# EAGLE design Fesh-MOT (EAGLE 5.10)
MFG: Nippon Chemi; PN: APXE160ARA390ME61G

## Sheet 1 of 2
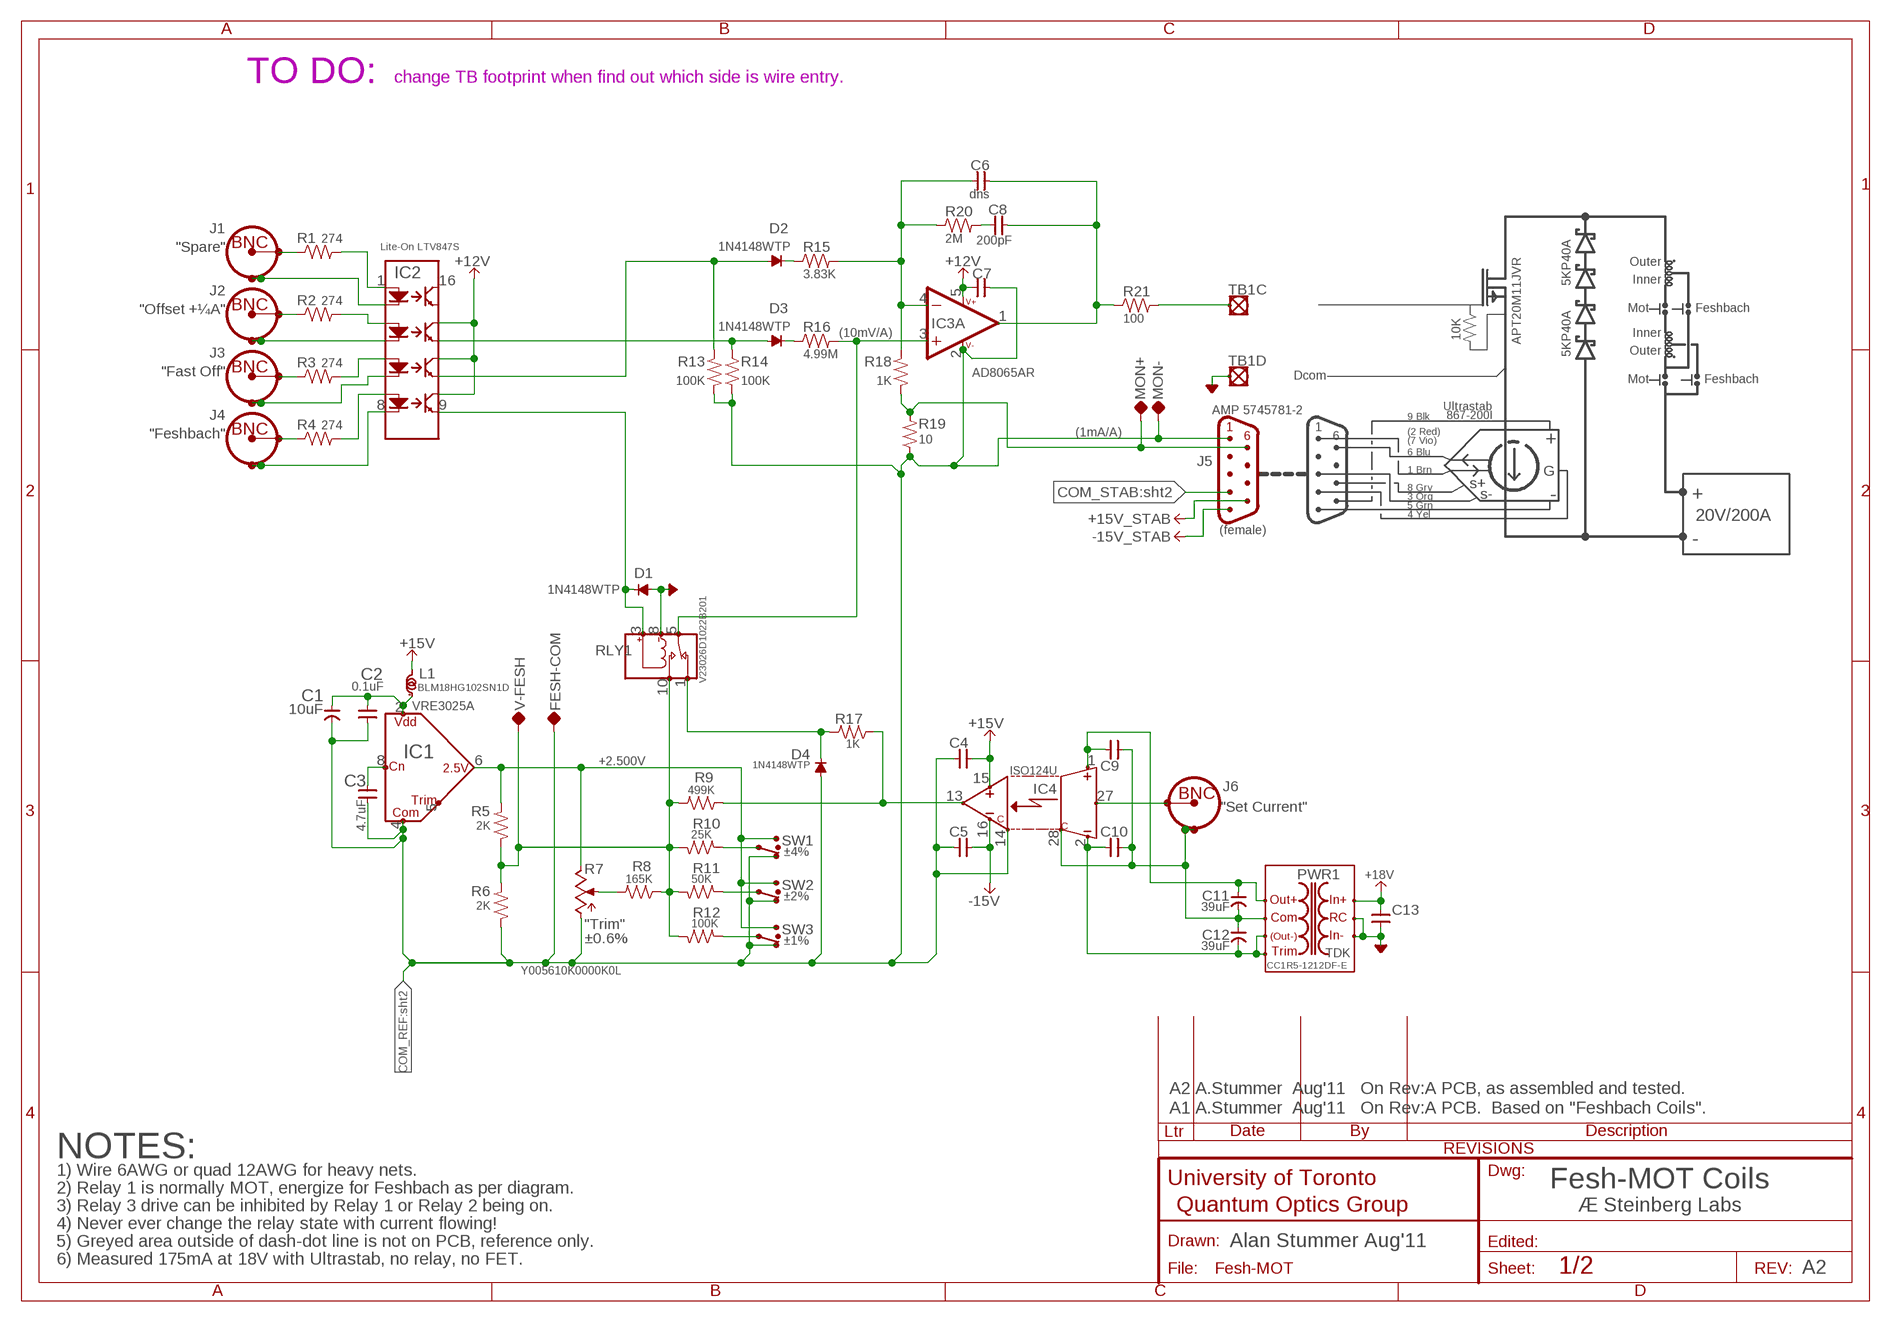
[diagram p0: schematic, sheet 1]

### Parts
C1  10uF  CAP-POL--NICHICON_F91_C  [CAP:NICHICON_F91_C]
C2  0.1uF  CAP-V-0805  [2012(0805)]
C3  4.7uF  CAP-V-0805  [2012(0805)]
C4  0.1uF  CAP-H-0805  [2012(0805)]
C5  0.1uF  CAP-H-0805  [2012(0805)]
C6  dns  CAP-H-0805  [2012(0805)]
C7  0.1uF  CAP-H-0805  [2012(0805)]
C8  200pF  CAP-H-0805  [2012(0805)]
C9  0.1uF  CAP-H-0805  [2012(0805)]
C10  0.1uF  CAP-H-0805  [2012(0805)]
C11  39uF  CAP-POL--NIPPONCHEM_E61  [CAP:NIPPONCHEM_E61]
C12  39uF  CAP-POL--NIPPONCHEM_E61  [CAP:NIPPONCHEM_E61]
C13  0.1uF  CAP-H-0805  [2012(0805)]
D1  1N4148WTP  DIODE,GENERIC-SOD123  [SOD123]
D2  1N4148WTP  DIODE,GENERIC-SOD123  [SOD123]
D3  1N4148WTP  DIODE,GENERIC-SOD123  [SOD123]
D4  1N4148WTP  DIODE,GENERIC-SOD123  [SOD123]
FESH-COM  TP-0.052"  [TP-0.052]
IC1  VRE3025A  VRE3025(2.5V_PRECISION_REF)  [THALER_SMT8]
IC2  Lite-On LTV847S  PC847P  [DIL16]
IC3  AD8065AR  OPAMP-SOT23-5  [SOT23-5]
IC4  ISO124U  ANALOG:ISOLATOR_ISO12X-SOIC28B  [SOIC28B]
J1  CONN-BNCTYPE3HORIZ  [CONN-BNC-AMP-TYPE3HORIZ]
J2  CONN-BNCTYPE3HORIZ  [CONN-BNC-AMP-TYPE3HORIZ]
J3  CONN-BNCTYPE3HORIZ  [CONN-BNC-AMP-TYPE3HORIZ]
J4  CONN-BNCTYPE3HORIZ  [CONN-BNC-AMP-TYPE3HORIZ]
J5  AMP 5745781-2  CONN:DB9-#2-AMP_745131  [CONN:DB9-H/V1]
J6  CONN-BNCTYPE3HORIZ  [CONN-BNC-AMP-TYPE3HORIZ]
L1  BLM18HG102SN1D  INDUCTOR-0603  [1608(0603)]
MON+  TP-0.052"  [TP-0.052]
MON-  TP-0.052"  [TP-0.052]
PWR1  CC1R5-1212DF-E  DC-DC:CCP-__-E(TDK1.5-25W)-CC1R5-R-E  [DC-DC:CC1R5-XXXXX-R-E(TDK/LAMBDA)]
R1  274  R-H-0805  [2012(0805)]
R2  274  R-H-0805  [2012(0805)]
R3  274  R-H-0805  [2012(0805)]
R4  274  R-H-0805  [2012(0805)]
R5  2K  R-V-Z201(TEXASCOMPONENTS)  [RES:Z201_TEXASCOMPONENTS]
R6  2K  R-V-Z201(TEXASCOMPONENTS)  [RES:Z201_TEXASCOMPONENTS]
R7  Y005610K0000K0L  POT-BOURNS_3009P  [BOURNS_3009P]
R8  165K  R-V-5025(2010)(DOWN-TO-0805)  [5025(2010)(DOWN-TO-0805)]
R9  499K  R-V-0805  [2012(0805)]
R10  25K  R-V-VH_02(TEXASCOMPONENTS)  [RES:VH_02,TEXASCOMPONENTS]
R11  50K  R-V-VH_02(TEXASCOMPONENTS)  [RES:VH_02,TEXASCOMPONENTS]
R12  100K  R-V-VH_02(TEXASCOMPONENTS)  [RES:VH_02,TEXASCOMPONENTS]
R13  100K  R-V-0805  [2012(0805)]
R14  100K  R-V-0805  [2012(0805)]
R15  3.83K  R-H-0805  [2012(0805)]
R16  4.99M  R-H-0805  [2012(0805)]
R17  1K  R-V-0805  [2012(0805)]
R18  1K  R-V-0805  [2012(0805)]
R19  10  R-V-Z206(TEXASCOMPONENTS)  [RES:Z206_TEXASCOMPONENTS]
R20  2M  R-H-0805  [2012(0805)]
R21  100  R-H-0805  [2012(0805)]
RLY1  V23026D1022B201  RELAY:SPDT-TYCO_V23026(SMT)  [RELAY:SPDT-TYCO_V23026]
SW1  ±4%  SWITCH:SPDT_CJS-1200A1  [SWITCH:SPDT-DIP(COPAL)]
SW2  ±2%  SWITCH:SPDT_CJS-1200A1  [SWITCH:SPDT-DIP(COPAL)]
SW3  ±1%  SWITCH:SPDT_CJS-1200A1  [SWITCH:SPDT-DIP(COPAL)]
TB1  TB-4-TYCO_1776244-4  [TB,BARRIER:1776244-4(TYCO,4,PCB,5MM)]
V-FESH  TP-0.052"  [TP-0.052]

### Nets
+2.500V: IC1.6(OUT) R5.THIS R7.CW SW1.1(NO\UP\RIGHT) SW2.1(NO\UP\RIGHT) SW3.1(NO\UP\RIGHT)
+12V [Wider]: C7.1 IC2.10(C4) IC2.12(C3) IC2.14(C2) IC3.5(B:V++) ; also sheet 2
+15V [Wider]: C4.1 IC4.15(OUT+V) L1.2(B) ; also sheet 2
+15V_STAB [Wider]: J5.9 ; also sheet 2
+15VA: C9.2 C11.POS IC4.1(IN+V) PWR1.+VOUT(+OUT)
+18V [Wider]: C13.1 PWR1.+VIN(+IN) ; also sheet 2
-15V: C5.1 IC4.16(OUT-V)
-15V_STAB [Wider]: J5.5 ; also sheet 2
-15VA: C10.2 C12.NEG IC4.2(IN-V) PWR1.-VOUT(-OUT) PWR1.TRM(TRIM)
AGND: C13.2 D1.A PWR1.-VIN(-IN) PWR1.RC RLY1.8(COIL-) TB1.4 ; also sheet 2
COM-A: C9.1 C10.1 C11.NEG C12.POS IC4.28(IN-COM) J6.SHIELD1 J6.SHIELD2 PWR1.COM
COM_REF [Wider]: C1.-(NEG) C2.1 C3.1 C4.2 C5.2 C7.2 D4.A FESH-COM.TP IC1.4(COM) IC3.2(B:V-) IC4.14(OUT-COM) J5.1 MON-.TP R6.OTHER R7.CCW R13.1 R14.1 R19.OTHER SW1.2(NC\DOWN\LEFT) SW2.2(NC\DOWN\LEFT) SW3.2(NC\DOWN\LEFT) ; also sheet 2
COM_STAB [Wider]: J5.4 ; also sheet 2
DRV: C6.2 C8.2 IC3.1(A:OUT) R21.1
N$1: C3.2 IC1.8(NOISECAP)
N$2 [Wider]: J5.6 MON+.TP R18.1 R19.THIS
N$4: J1.CONDUCTOR R1.1
N$5: D4.C R17.2 RLY1.1(NC)
N$6: J2.CONDUCTOR R2.1
N$7: IC4.13(OUT) R9.1 R17.1
N$8: C6.1 IC3.4(A:-IN) R15.2 R18.2 R20.1
N$10: J3.CONDUCTOR R3.1
N$11: R5.OTHER R6.THIS R8.1 R9.2 R10.2 R11.2 R12.2 RLY1.10(NO) V-FESH.TP
N$12: J4.CONDUCTOR R4.1
N$13: IC2.1(A1) R1.2
N$15: D3.A IC2.13(E2) R14.2
N$16: D1.C IC2.9(E4) RLY1.3(COIL+)
N$17: IC3.3(A:+IN) R16.2 RLY1.5(COM)
N$18: IC2.3(A2) R2.2
N$19: C1.+(POS) C2.2 IC1.2(VDD) L1.1(A)
N$20: D3.C R16.1
N$21: IC2.5(A3) R3.2
N$22: IC2.7(A4) R4.2
N$23: IC4.27(IN) J6.CONDUCTOR
N$24: C8.1 R20.2
N$25: R10.1 SW1.COM
N$26: R7.WIPER(W) R8.2
N$28: IC2.2(K1) J1.SHIELD1 J1.SHIELD2
N$29: IC2.4(K2) J2.SHIELD1 J2.SHIELD2
N$31: IC2.6(K3) J3.SHIELD1 J3.SHIELD2
N$32: R11.1 SW2.COM
N$33: R12.1 SW3.COM
N$42: R21.2 TB1.3
N$43: IC2.8(K4) J4.SHIELD1 J4.SHIELD2
N$45: D2.C R15.1
OFF: D2.A IC2.11(E3) R13.2
Unconnected: IC1.5(TRIM) IC2.15(E1) IC2.16(C1) J5.2 J5.3 J5.7 J5.8

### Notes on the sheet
- TO DO: | change TB footprint when find out which side is wire entry.
- "Spare"
- Outer
- 5KP40A | Inner
- "Offset +¼A" | Mot | Feshbach
- 10K
- (10mV/A) | Inner
- APT20M11JVR
- 5KP40A | Outer
- "Fast Off"
- Dcom
- Mot | Feshbach
- Ultrastab
- 9 Blk | 867-200I
- 1
- (1mA/A) | (2 Red)
- "Feshbach" | 6
- (7 Vio) | +
- 6 Blu
- 1 Brn | G
- 8 Gry | s+
- 3 Org | s- | - | +
- 5 Grn
- 4 Yel
- 20V/200A
- (female)
- -
- "Set Current"
- "Trim"
- ±0.6%
- A2 A.Stummer  Aug'11   On Rev:A PCB, as assembled and tested.
- A1 A.Stummer  Aug'11   On Rev:A PCB.  Based on "Feshbach Coils".
- NOTES:
- 1) Wire 6AWG or quad 12AWG for heavy nets.
- Fesh-MOT Coils
- 2) Relay 1 is normally MOT, energize for Feshbach as per diagram.
- 3) Relay 3 drive can be inhibited by Relay 1 or Relay 2 being on. | Æ Steinberg Labs
- 4) Never ever change the relay state with current flowing!
- 5) Greyed area outside of dash-dot line is not on PCB, reference only. | Alan Stummer Aug'11
- 6) Measured 175mA at 18V with Ultrastab, no relay, no FET.
- A2

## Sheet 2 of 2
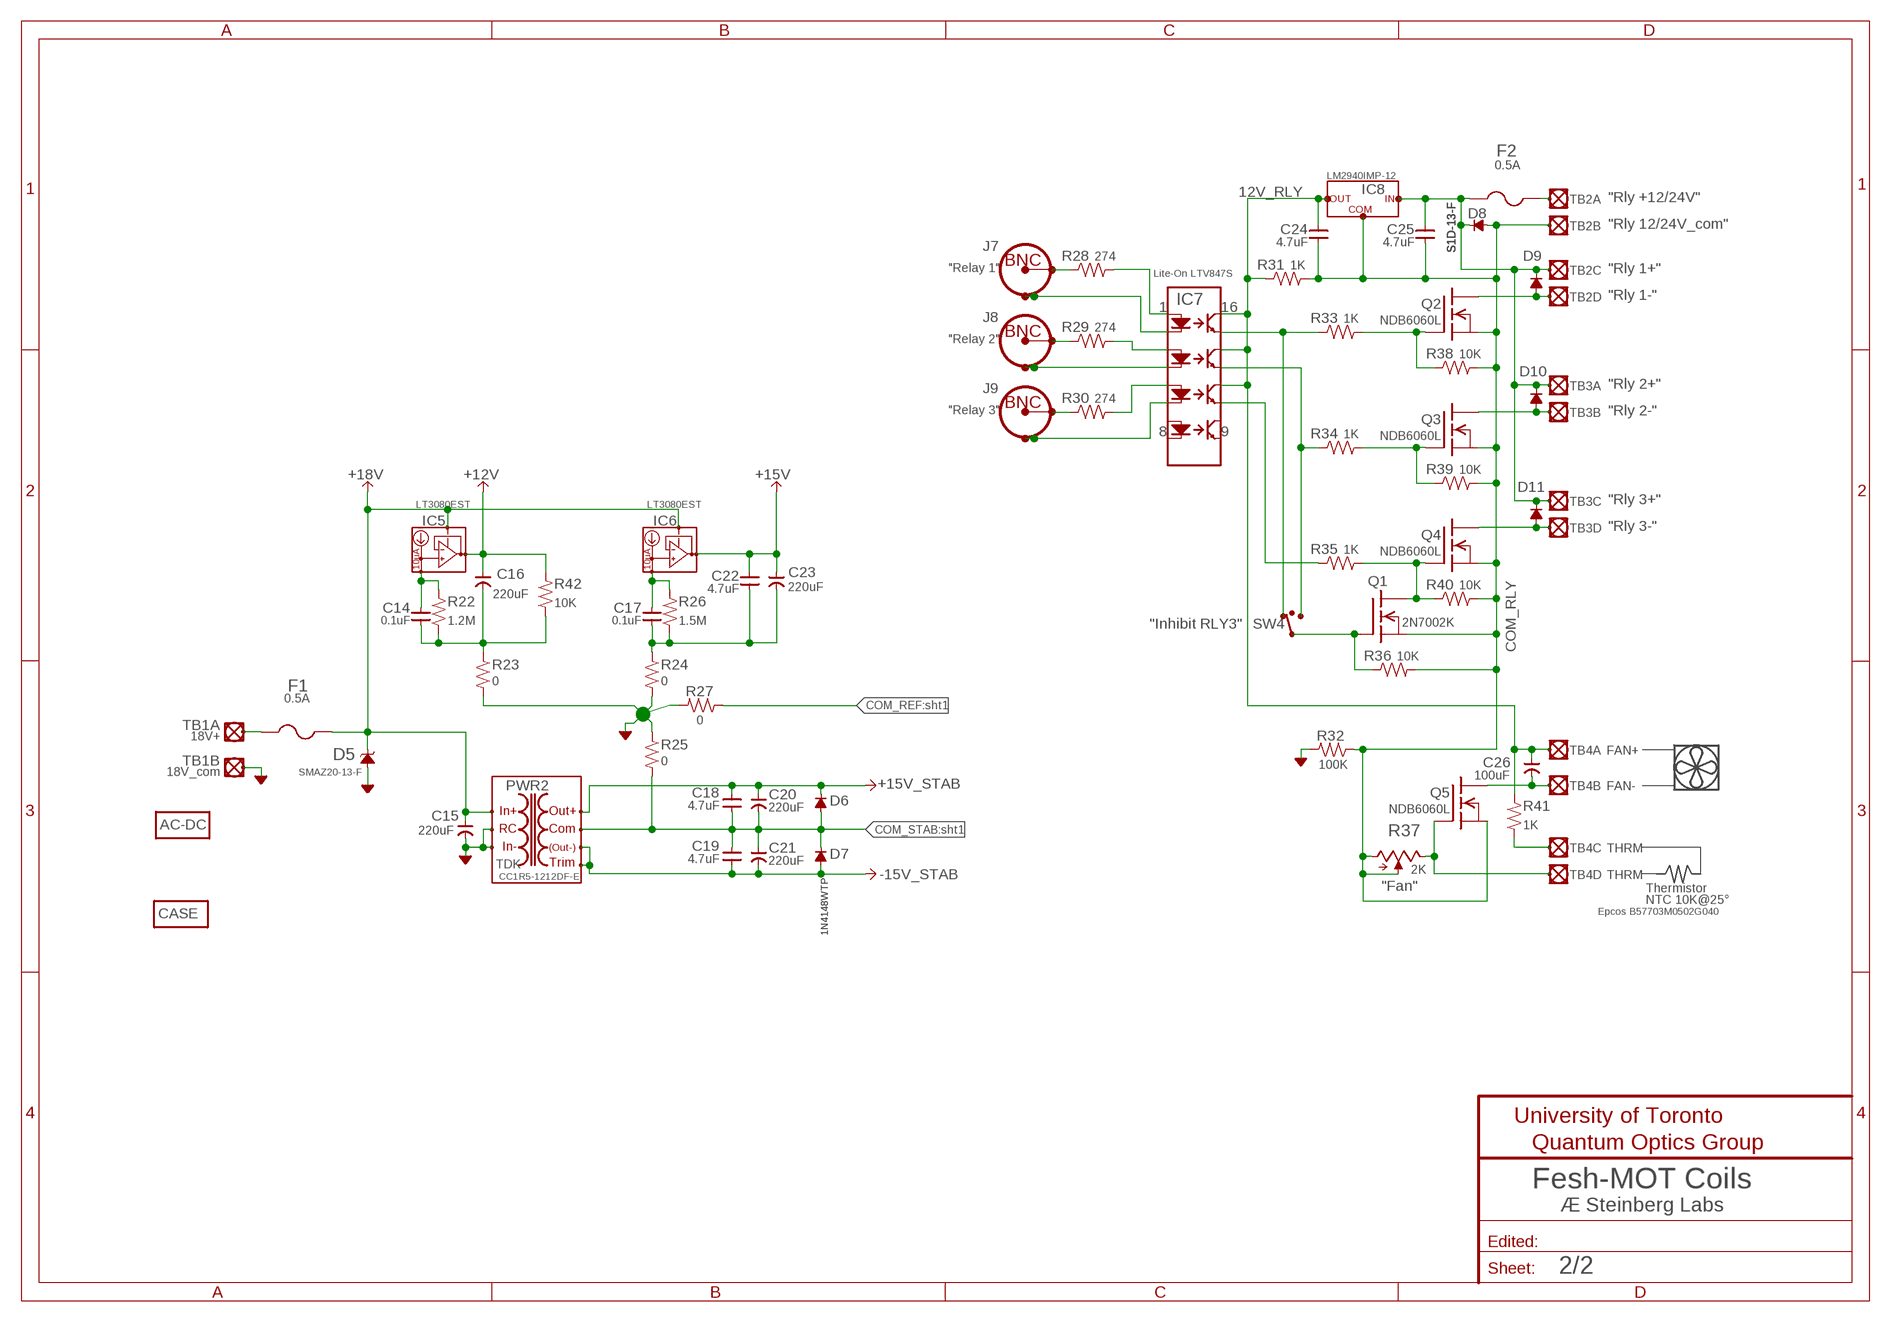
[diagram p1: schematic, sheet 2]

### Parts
AC-DC  MISC  [MISC]
C14  0.1uF  CAP-V-0805  [2012(0805)]
C15  220uF  CAP-POL--NIPPONCHEM_H70_H80  [CAP:NIPPONCHEM_H70_H80_HA0]
C16  220uF  CAP-POL--NIPPONCHEM_H70_H80  [CAP:NIPPONCHEM_H70_H80_HA0]
C17  0.1uF  CAP-V-0805  [2012(0805)]
C18  4.7uF  CAP-V-0805  [2012(0805)]
C19  4.7uF  CAP-V-0805  [2012(0805)]
C20  220uF  CAP-POL--NIPPONCHEM_H70_H80  [CAP:NIPPONCHEM_H70_H80_HA0]
C21  220uF  CAP-POL--NIPPONCHEM_H70_H80  [CAP:NIPPONCHEM_H70_H80_HA0]
C22  4.7uF  CAP-V-0805  [2012(0805)]
C23  220uF  CAP-POL--NIPPONCHEM_H70_H80  [CAP:NIPPONCHEM_H70_H80_HA0]
C24  4.7uF  CAP-V-0805  [2012(0805)]
C25  4.7uF  CAP-V-0805  [2012(0805)]
C26  100uF  CAP-POL--NIPPONCHEM_H70_H80  [CAP:NIPPONCHEM_H70_H80_HA0]
CASE  MISC  [MISC]
D5  SMAZ20-13-F  ZENER-EIA-A  [EIA-A(SMA)]
D6  1N4148WTP  DIODE,GENERIC-SOD123  [SOD123]
D7  1N4148WTP  DIODE,GENERIC-SOD123  [SOD123]
D8  S1D-13-F  DIODE,GENERIC-SMA  [EIA-A(SMA)]
D9  S1D-13-F  DIODE,GENERIC-SMA  [EIA-A(SMA)]
D10  S1D-13-F  DIODE,GENERIC-SMA  [EIA-A(SMA)]
D11  S1D-13-F  DIODE,GENERIC-SMA  [EIA-A(SMA)]
F1  0.5A  FUSE-5X20-4  [FUSE]
F2  0.5A  FUSE-5X20-4  [FUSE]
IC5  LT3080EST  REGULATOR:LT3080(3PIN,LDO,I-SET)-SOT223  [SOT223(C)]
IC6  LT3080EST  REGULATOR:LT3080(3PIN,LDO,I-SET)-SOT223  [SOT223(C)]
IC7  Lite-On LTV847S  PC847P  [DIL16]
IC8  LM2940IMP-12  REGULATOR:3PIN-SOT223(TAB,2PINS)  [SOT223(C)]
J7  "Relay 1"  CONN-BNCTYPE3HORIZ  [CONN-BNC-AMP-TYPE3HORIZ]
J8  "Relay 2"  CONN-BNCTYPE3HORIZ  [CONN-BNC-AMP-TYPE3HORIZ]
J9  "Relay 3"  CONN-BNCTYPE3HORIZ  [CONN-BNC-AMP-TYPE3HORIZ]
PWR2  CC1R5-1212DF-E  DC-DC:CCP-__-E(TDK1.5-25W)-CC1R5-R-E  [DC-DC:CC1R5-XXXXX-R-E(TDK/LAMBDA)]
Q1  2N7002K  MOSFET-N-SOT23(2N7000/2)  [SOT23]
Q2  NDB6060L  FET-N:NDB6060L(6A,48V,LOGIC)  [TO263]
Q3  NDB6060L  FET-N:NDB6060L(6A,48V,LOGIC)  [TO263]
Q4  NDB6060L  FET-N:NDB6060L(6A,48V,LOGIC)  [TO263]
Q5  NDB6060L  FET-N:NDB6060L(6A,48V,LOGIC)  [TO263]
R22  1.2M  R-V-0805  [2012(0805)]
R23  0  R-H-0805  [2012(0805)]
R24  0  R-H-0805  [2012(0805)]
R25  0  R-H-0805  [2012(0805)]
R26  1.5M  R-V-0805  [2012(0805)]
R27  0  R-H-0805  [2012(0805)]
R28  274  R-H-0805  [2012(0805)]
R29  274  R-H-0805  [2012(0805)]
R30  274  R-H-0805  [2012(0805)]
R31  1K  R-H-0805  [2012(0805)]
R32  100K  R-H-0805  [2012(0805)]
R33  1K  R-H-0805  [2012(0805)]
R34  1K  R-H-0805  [2012(0805)]
R35  1K  R-H-0805  [2012(0805)]
R36  10K  R-H-0805  [2012(0805)]
R37  2K  POT-BOURNS_3296Y  [BOURNS:3296Y]
R38  10K  R-H-0805  [2012(0805)]
R39  10K  R-H-0805  [2012(0805)]
R40  10K  R-H-0805  [2012(0805)]
R41  1K  R-V-0805  [2012(0805)]
R42  10K  R-V-0805  [2012(0805)]
SW4  ±4%  SWITCH:SPDT_CJS-1200A1  [SWITCH:SPDT-DIP(COPAL)]
TB2  TB-4-TYCO_1776244-4  [TB,BARRIER:1776244-4(TYCO,4,PCB,5MM)]
TB3  TB-4-TYCO_1776244-4  [TB,BARRIER:1776244-4(TYCO,4,PCB,5MM)]
TB4  TB-4-TYCO_1776244-4  [TB,BARRIER:1776244-4(TYCO,4,PCB,5MM)]

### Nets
12V_RLY [Wider]: C24.2 C26.POS IC7.12(C3) IC7.14(C2) IC7.16(C1) IC8.3(OUT) R31.1 R41.2 TB4.1
18V+: F1.1A TB1.1
+12V [Wider]: C16.POS IC5.2(OUT) R42.2 ; also sheet 1
+15V [Wider]: C22.2 C23.POS IC6.2(OUT) ; also sheet 1
+15V_STAB [Wider]: C18.2 C20.POS D6.C PWR2.+VOUT(+OUT) ; also sheet 1
+18V [Wider]: C15.POS D5.K(C) F1.2A IC5.3(IN) IC6.3(IN) PWR2.+VIN(+IN) ; also sheet 1
-15V_STAB [Wider]: C19.1 C21.NEG D7.A PWR2.-VOUT(-OUT) PWR2.TRM(TRIM) ; also sheet 1
AGND: C15.NEG D5.A PWR2.-VIN(-IN) PWR2.RC R23.2 R24.2 R25.1 R27.2 R32.2 TB1.2 ; also sheet 1
COM_REF [Wider]: R27.1 ; also sheet 1
COM_RLY [Wider]: C24.1 C25.1 D8.A IC8.2(COM) Q1.2(S) Q2.3(S) Q3.3(S) Q4.3(S) Q5.3(S) R31.2 R32.1 R36.2 R37.CCW R37.W R38.2 R39.2 R40.2 TB2.2
COM_STAB [Wider]: C18.1 C19.2 C20.NEG C21.POS D6.A D7.C PWR2.COM R25.2 ; also sheet 1
FAN- [Wider]: C26.NEG Q5.2(D) TB4.2
N$3 [Wider]: C17.1 C22.1 C23.NEG R24.1 R26.1
N$9 [Wider]: F2.2A TB2.1
N$14 [Wider]: D9.A Q2.2(D) TB2.4
N$27: C17.2 IC6.1(SET) R26.2
N$30: J7.CONDUCTOR R28.1
N$34: Q1.1(G) R36.1 SW4.COM
N$35: J8.CONDUCTOR R29.1
N$36: J9.CONDUCTOR R30.1
N$37 [Wider]: R41.1 TB4.3
N$38: Q2.1(G) R33.2 R38.1
N$39: IC7.1(A1) R28.2
N$40: IC7.3(A2) R29.2
N$41: C14.2 IC5.1(SET) R22.2
N$44: IC7.5(A3) R30.2
N$46: IC7.15(E1) R33.1 SW4.2(NC\DOWN\LEFT)
N$47: IC7.2(K1) J7.SHIELD1 J7.SHIELD2
N$48: IC7.4(K2) J8.SHIELD1 J8.SHIELD2
N$49: IC7.6(K3) J9.SHIELD1 J9.SHIELD2
N$50: IC7.13(E2) R34.1 SW4.1(NO\UP\RIGHT)
N$51 [Wider]: D10.A Q3.2(D) TB3.2
N$52: IC7.11(E3) R35.1
N$53: Q3.1(G) R34.2 R39.1
N$54 [Wider]: C14.1 C16.NEG R22.1 R23.1 R42.1
N$55 [Wider]: D11.A Q4.2(D) TB3.4
N$57: Q1.3(D) Q4.1(G) R35.2 R40.1
RLY+ [Wider]: C25.2 D8.K(C) D9.K(C) D10.K(C) D11.K(C) F2.1A IC8.1(VI) TB2.3 TB3.1 TB3.3
THRM: Q5.1(G) R37.CW TB4.4
Unconnected: IC7.7(A4) IC7.8(K4) IC7.9(E4) IC7.10(C4)

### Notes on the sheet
- "Rly +12/24V"
- "Rly 12/24V_com"
- "Rly 1+"
- "Rly 1-"
- "Rly 2+"
- "Rly 2-"
- "Rly 3+"
- "Rly 3-"
- "Inhibit RLY3"
- FAN+
- 18V_com
- Thermistor
- "Fan"
- NTC 10K@25°
- Epcos B57703M0502G040
- Fesh-MOT Coils
- Æ Steinberg Labs

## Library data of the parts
AC-DC CASE = QuantumOptics:MISC: Miscellaneous Part, just a placeholder for miscellaeous parts
C1 C11 C12 C15 C16 C20 C21 C23 C26 = QuantumOptics:CAP-POL-: Capacitor, Polarized, SMT 0805 and up, probably tantalum.
C2 C3 C14 C17-C19 C22 C24 C25 = QuantumOptics:CAP-V-: Cap, SMT and Through-hole, 0402 and up.
C4-C10 C13 = QuantumOptics:CAP-H-: Cap, SMT and Through-hole, 0402 and up.
D1-D4 D6-D11 = QuantumOptics:DIODE,GENERIC: Diode, Generic, plain old vanilla diodes.
D5 = QuantumOptics:ZENER: Zener
F1 F2 = QuantumOptics:FUSE: Fuse
FESH-COM MON+ MON- V-FESH = QuantumOptics:TP: Testpoint, either SMT pad, small hole or loop style TP such as Keystone 5002K (0.042").
IC1 = QuantumOptics:VRE3025(2.5V_PRECISION_REF): VRE3025, precision +2.5V reference, Thaler, ±0.6ppm/°. http://thaler.com/thcpdf/vre3025.pdf
IC2 IC7 = QuantumOptics:PC847: Photocoupler, quad, CTR > 50%.
IC3 = QuantumOptics:OPAMP: Op Amp, generic, pick the right package. e.g. AD8605: SOT-23-5, RRIO, 10MHz, Ib = 1pA, Vio < 65uV, 2.7-5.5V.
IC4 = QuantumOptics:ANALOG:ISOLATOR_ISO12X: Analog Isolator, ISO12x T.I., ±10V gain=1. http://focus.ti.com/lit/ds/symlink/iso124.pdf
IC5 IC6 = QuantumOptics:REGULATOR:LT3080(3PIN,LDO,I-SET): LT3080, LDO, output set by single resistor, nice part, LinTech, 1A, SOT223, MSOP8, TO220. http://cds.linear.com/docs/Datasheet/3080f.pdf
IC8 = QuantumOptics:REGULATOR:3PIN: LM1086-xxx, National Semiconductor, LDO, adjustable or fixed. http://cache.national.com/ds/LM/LM1086.pdf
J1-J4 J6-J9 = QuantumOptics:CONN-BNC: BNC PCB, horizontal or vertical, e.g. vertical: Amp 227677-1, nut 1-329631-2, shoulder washer 330620. The two shield connections allow the assembly on either side of the board. Horiz isolated: 5227222-6, http://catalog.tycoelectronics.com/TE/bin/TE.Connect?C=1&M=BYPN&TCPN=5227222-6&RQPN=5227222-6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
J5 = QuantumOptics:CONN:DB9-#2: DB-9 Connector
L1 = QuantumOptics:INDUCTOR: Inductor, generic inductor.
PWR1 PWR2 = QuantumOptics:DC-DC:CCP-__-E(TDK1.5-25W): CCp-inoutsc-E, TDK DC-DC isolated, 1.5-25W, uni- or bipolar "p": 1.5, 3, 6, 10, 15, or 25W. "in": Input 05, 12, 24 or 48V. "out": Output 3.3, 5, 12, ±12 (or 24), ±15 (or30V). "s": Polarity single or dual. "c": Case horiz DIP, horiz SMD or vertical SIP. http://www.tdk.co.jp/tefe02/ea335_cc_e.pdf
Q1 = QuantumOptics:MOSFET-N: Mosfet, N-Channel, generic enhancement mode N-FET.
Q2-Q5 = QuantumOptics:FET-N:NDB6060L(6A,48V,LOGIC): NDB6060L, Fairchild et al., logic level, 6A 48V, TO-263. http://www.fairchildsemi.com/ds/ND/NDB6060L.pdf
R1-R4 R15 R16 R20 R21 R23-R25 R27-R36 R38-R40 = QuantumOptics:R-H-*: Resistor, SMT & Through-Hole, horizontal symbol
R5 R6 R8-R14 R17-R19 R22 R26 R41 R42 = QuantumOptics:R-V-*: Resistor, SMT & Through-Hole, vertical symbol
R7 R37 = QuantumOptics:POT: Pot, regular or trimpot
RLY1 = QuantumOptics:RELAY:SPDT: SPDT Relay
SW1-SW4 = QuantumOptics:SWITCH:SPDT: Switch, SPDT
TB1-TB4 = QuantumOptics:TB-4: 4 position terminal block, e.g. Molex 38720-6304 (0.375", screw for ring tab), or, Tyco 1776244-4 (5mm, top screw)

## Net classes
1 Wider: width 0.508 mm
3 +67V: width 0.178 mm, drill 0.508 mm, clearance 0.635 mm

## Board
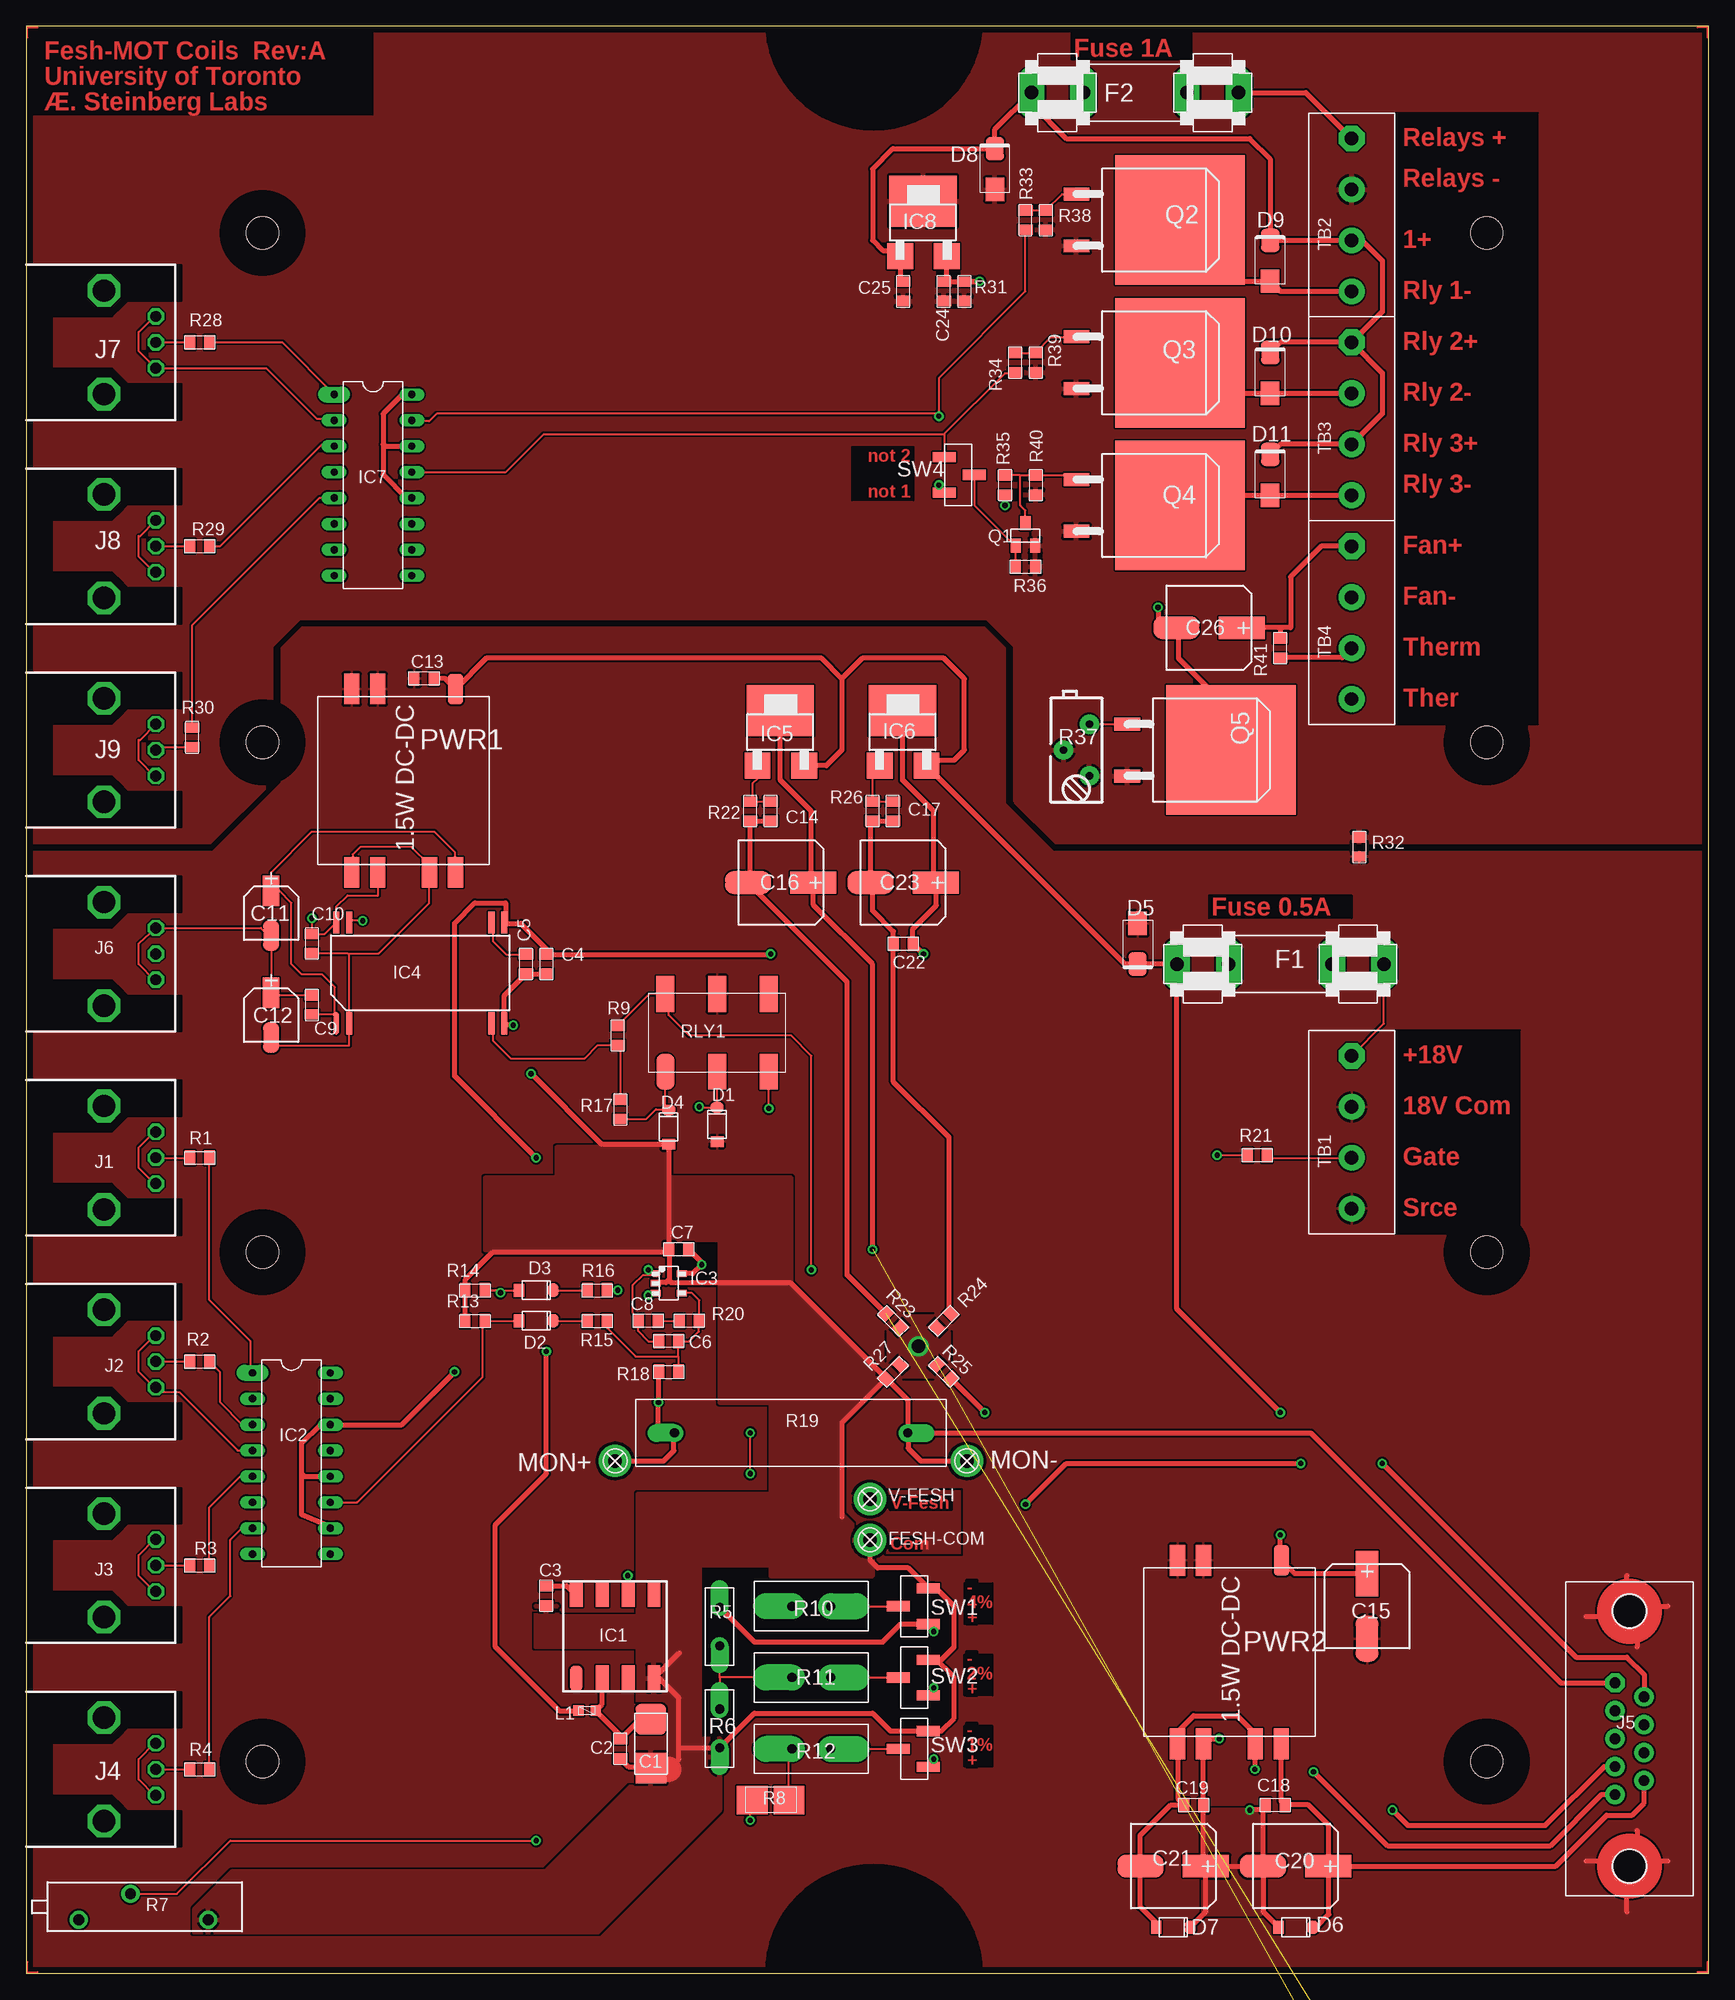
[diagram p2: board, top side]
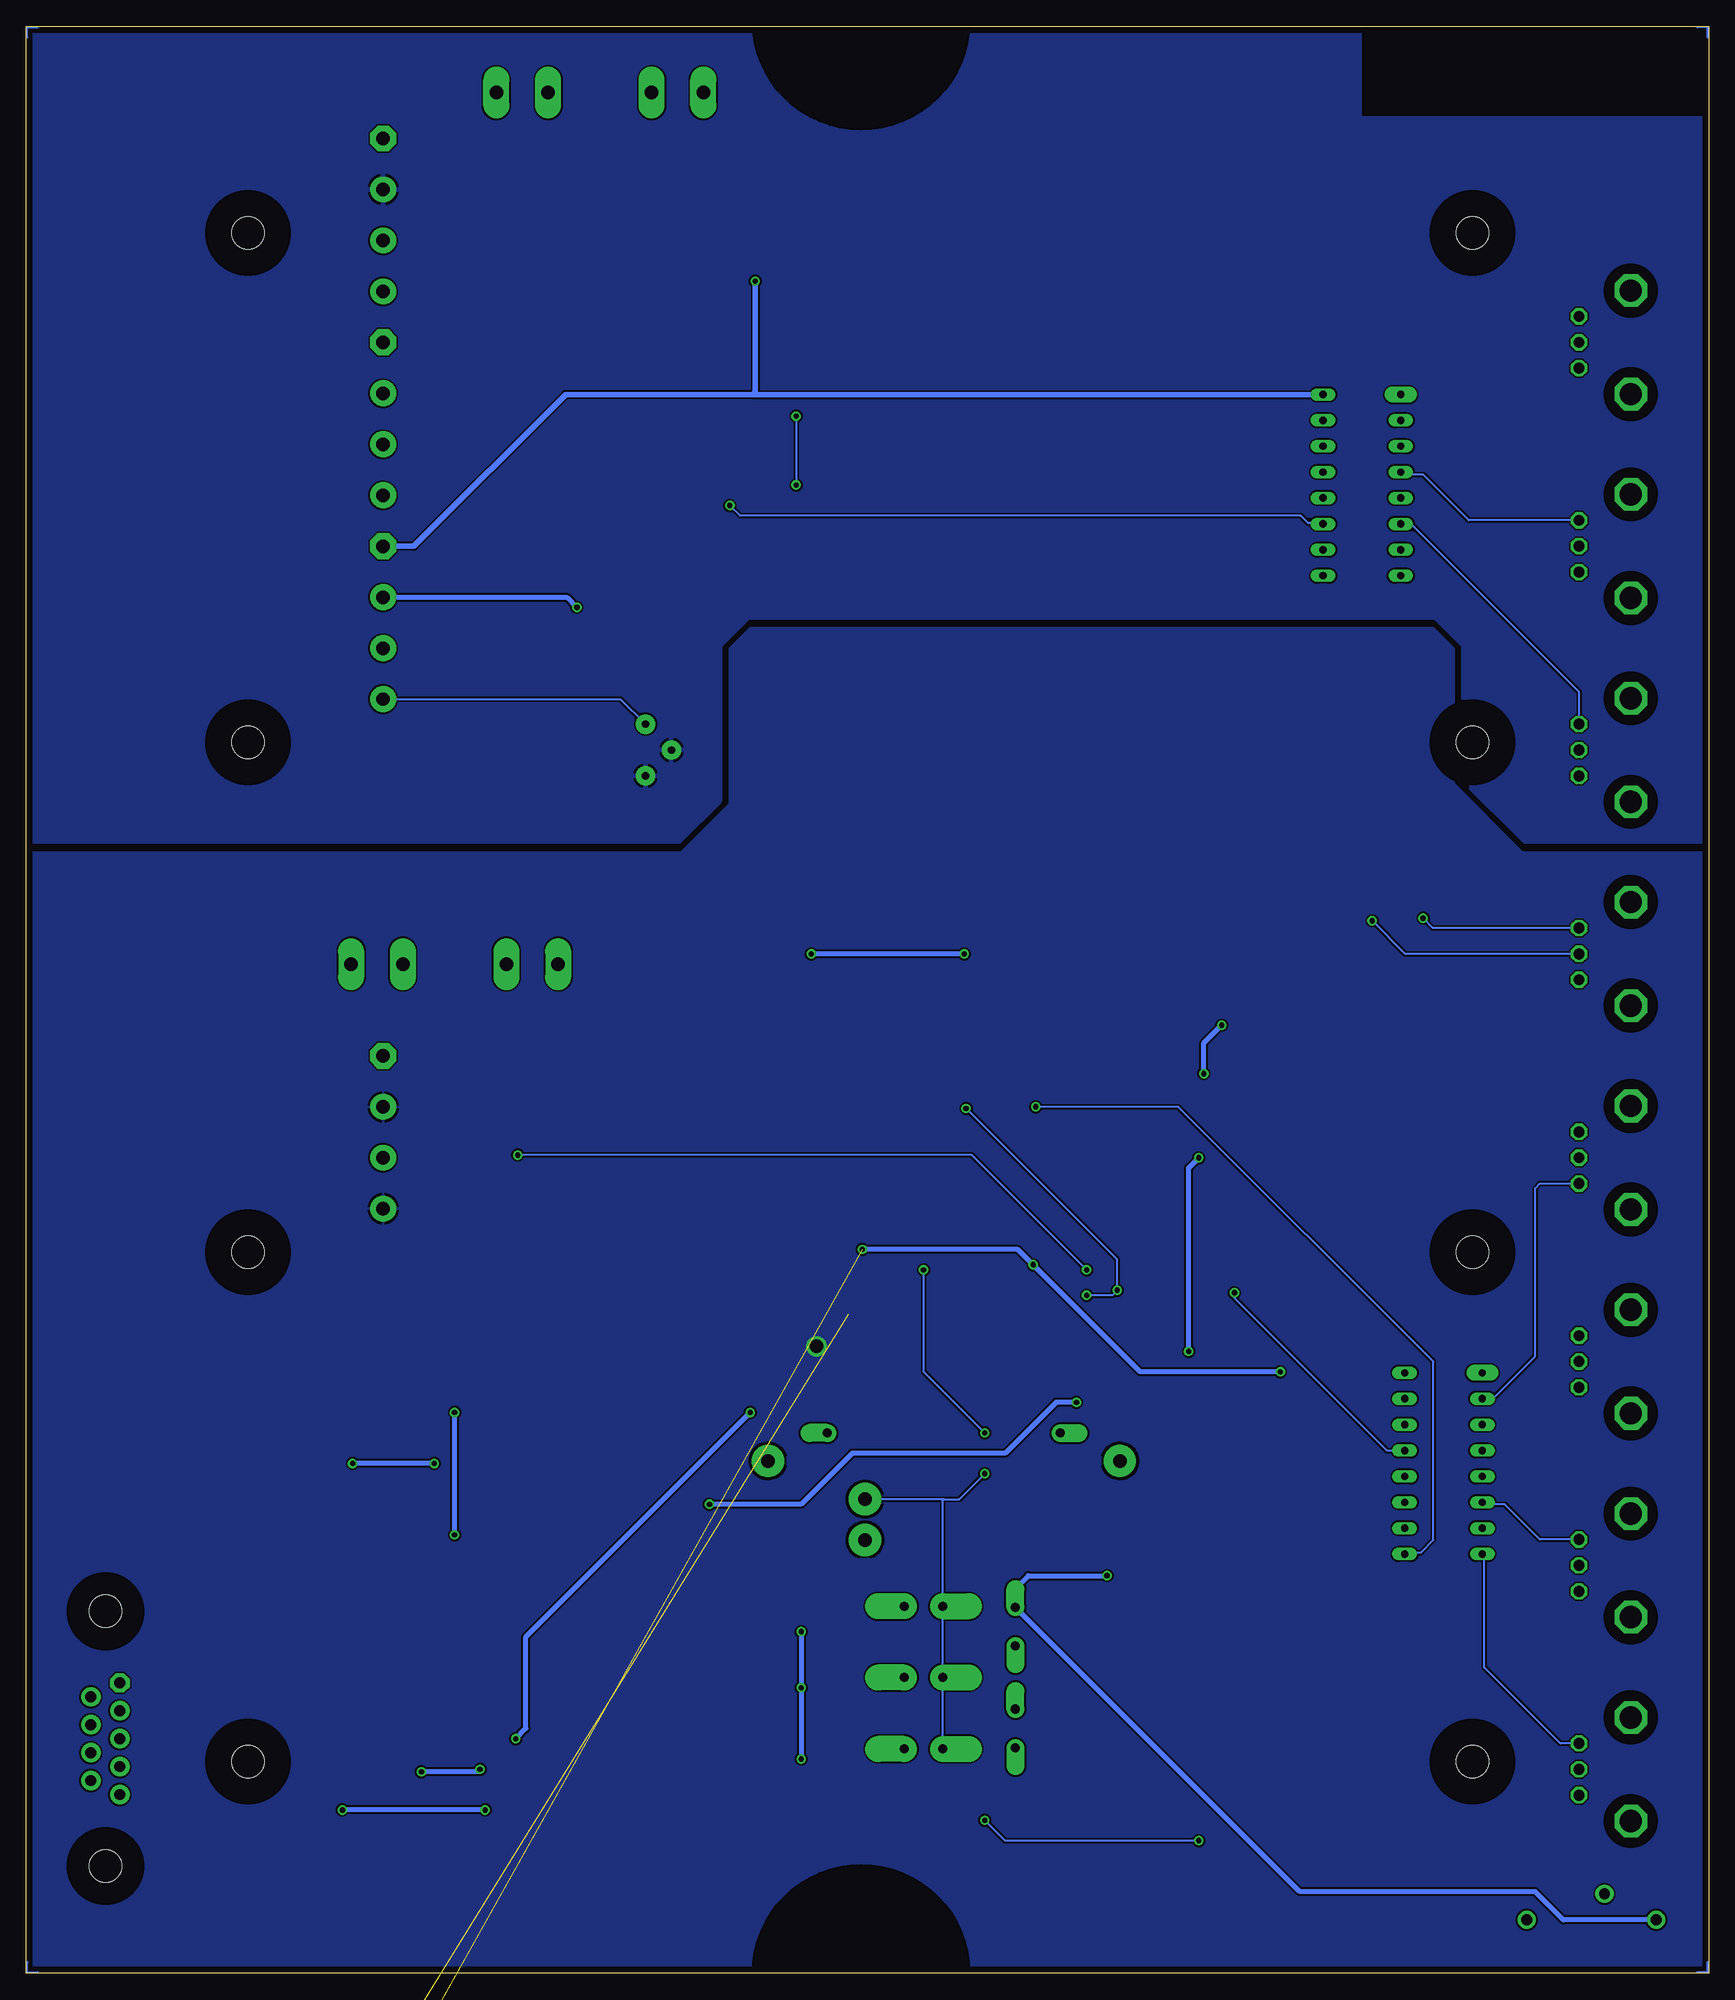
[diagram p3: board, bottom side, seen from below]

Size 165 x 191 mm. Coordinates in mm from the lower left corner, seen from the top.
Outline: 0,0 165,0 165,191 0,191 0,0
Copper layers (1+16): Top 0.035mm / dielectric 1.5mm / Bottom 0.035mm
Design rules "DRC standard check": minimum track width 7mil, minimum drill 20mil, track to track 7mil, track to pad 7mil, pad to pad 7mil, via to via 7mil, smd to smd 0mil, copper to edge 25mil, drill to drill 8mil, minimum pad ring 10mil, minimum via ring 8mil, stop-mask expansion 4mil, vias tented up to drill 0mil, thermal gap 10mil
Holes 3.17 mm at 143.25,20.75 143.25,70.75 143.25,120.75 143.25,170.75 23.15,170.75 23.15,120.75 23.15,70.75 23.15,20.75
tRestrict: area 140.4,17.9 to 146.1,23.6; area 140.4,68 to 146.1,73.5; area 140.4,118 to 146.1,123.5; area 140.4,167.9 to 146.1,173.6; area 20.3,167.9 to 25.9,173.6; area 20.3,118 to 25.9,123.5; area 20.3,68 to 25.9,73.5; area 20.3,17.9 to 25.9,23.6; 43 lines
bRestrict: area 140.4,17.9 to 146.1,23.6; area 140.4,68 to 146.1,73.5; area 140.4,118 to 146.1,123.5; area 140.4,167.9 to 146.1,173.6; area 20.3,167.9 to 25.9,173.6; area 20.3,118 to 25.9,123.5; area 20.3,68 to 25.9,73.5; area 20.3,17.9 to 25.9,23.6; 2 lines

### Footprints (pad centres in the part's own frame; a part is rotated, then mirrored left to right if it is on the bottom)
CAP:NICHICON_F91_C = smd 3 x 3: + -2.4,0; - 2.4,0
2012(0805) = smd 1.016 x 1.397: 1 -0.953,0; 2 0.953,0
CAP:NIPPONCHEM_E61 = smd 3 x 1.6: NEG -2.2,0; POS 2.2,0
CAP:NIPPONCHEM_H70_H80_HA0 = smd 4.5 x 2.2: NEG -3.2,0; POS 3.2,0
SOD123 = smd 1.016 x 1.27: A 1.676,0; C -1.676,0
EIA-A(SMA) = smd 2.3 x 1.8: A -2,0; K 2,0
FUSE = drill 1.321 pad 2.54 long: 1A -10.16,0; 1B -5.08,0; 2A 10.16,0; 2B 5.08,0
TP-0.052 = drill 1.321 pad 3.175 round: TP 0,0
THALER_SMT8 = smd 1.27 x 2.54: 1 -3.81,-3.81; 2 -1.27,-3.81; 3 1.27,-3.81; 4 3.81,-3.81; 5 3.81,4.445; 6 1.27,4.445; 7 -1.27,4.445; 8 -3.81,4.445
DIL16@1 = drill 0.711 pad 1.575 long: 1 -8.89,-3.81 | drill 0.711 long: 2 -6.35,-3.81; 3 -3.81,-3.81; 4 -1.27,-3.81; 5 1.27,-3.81; 6 3.81,-3.81; 7 6.35,-3.81; 8 8.89,-3.81; 9 8.89,3.81; 10 6.35,3.81; 11 3.81,3.81; 12 1.27,3.81; 13 -1.27,3.81; 14 -3.81,3.81; 15 -6.35,3.81; 16 -8.89,3.81
SOT23-5 = smd 0.635 x 0.991: 1 -0.635,-1.27; 2 0.318,-1.27; 3 1.27,-1.27; 4 1.27,1.27; 5 -0.635,1.27
SOIC28B = smd 0.6 x 2.2: 1 -7.62,-4.81; 2 -6.35,-4.81; 13 7.62,-4.81; 14 8.89,-4.81; 15 8.89,5.08; 16 7.62,5.08; 27 -6.35,5.08; 28 -7.62,5.08
SOT223(C) = smd 2.54 x 2.54: 1 -2.286,-2.54; 3 2.286,-2.54 | smd 6.6 x 5: 2 -0.05,2.87
DIL16@2 = drill 0.711 pad 1.575 long: 1 -8.89,-3.81 | drill 0.711 long: 2 -6.35,-3.81; 3 -3.81,-3.81; 4 -1.27,-3.81; 5 1.27,-3.81; 6 3.81,-3.81; 7 6.35,-3.81; 8 8.89,-3.81; 9 8.89,3.81; 10 6.35,3.81; 11 3.81,3.81; 12 1.27,3.81; 13 -1.27,3.81; 14 -3.81,3.81; 15 -6.35,3.81; 16 -8.89,3.81
CONN-BNC-AMP-TYPE3HORIZ = drill 1.067 octagon: CONDUCTOR 0,-12.7; SHIELD1 -2.54,-12.7; SHIELD2 2.54,-12.7 | drill 2.184 octagon: P$1 -5.08,-7.62; P$2 5.08,-7.62
CONN:DB9-H/V1 = drill 1.067 pad 1.905 octagon: 1 -5.48,-1.42 | drill 1.067 pad 1.905 round: 2 -2.74,-1.42; 3 0,-1.42; 4 2.74,-1.42; 5 5.48,-1.42; 6 -4.11,1.42; 7 -1.37,1.42; 8 1.37,1.42; 9 4.11,1.42 | hole 3.175: -12.5,0; 12.5,0
1608(0603) = smd 1.016 x 1.016: 1 -0.85,0; 2 0.85,0
DC-DC:CC1R5-XXXXX-R-E(TDK/LAMBDA) = smd 3 x 1.5: +VIN -9,5.1; +VOUT 9,5.08; -VIN -9,-5.08; -VOUT 9,-5.08; COM 9,-2.54; RC -9,-2.54; TRM 9,2.54
SOT23 = smd 1 x 1.4: 1 -0.953,-0.953; 2 0.953,-0.953; 3 0,1.27
TO263 = smd 1.27 x 2.54: 1 -2.54,0; 3 2.54,0 | smd 12.7 x 12.7: 2 0,10.16
RES:Z201_TEXASCOMPONENTS = drill 0.889 pad 1.778 offset: OTHER 1.905,0; THIS -1.905,0
BOURNS_3009P = drill 1.067 pad 1.778 round: CCW -5.08,1.27; CW 7.62,1.27; WIPER 2.54,-1.27
5025(2010)(DOWN-TO-0805) = smd 3 x 2.8: 1 -1.8,0; 2 1.8,0
RES:VH_02,TEXASCOMPONENTS = drill 0.889 pad 2.54 offset: 1 -1.905,0; 2 1.905,0
RES:Z206_TEXASCOMPONENTS = drill 0.889 pad 1.778 offset: OTHER 11.43,0; THIS -11.43,0
BOURNS:3296Y = drill 0.711 pad 1.905 round: CCW 2.54,1.27; CW -2.54,1.27; W 0,-1.27
RELAY:SPDT-TYCO_V23026 = smd 1.75 x 3.5: 1 -5.08,-3.81; 3 0,-3.81; 5 5.08,-3.81; 6 5.08,3.81; 8 0,3.81; 10 -5.08,3.81
SWITCH:SPDT-DIP(COPAL) = smd 1 x 2.25: 1 -1.75,-1.475; 2 1.75,-1.475; COM 0,1.475
TB,BARRIER:1776244-4(TYCO,4,PCB,5MM) = drill 1.321 pad 2.54 octagon: 1 0,0 | drill 1.321 pad 2.54 round: 2 -5,0; 3 -10,0; 4 -15,0

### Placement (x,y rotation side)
AC-DC  not placed on the board
C1  61.25,22.5 270 top
C2  58.25,22 90 top
C3  51,37 90 top
C4  51,99 270 top
C5  49,99 270 top
C6  63,62 180 top
C7  64,71 180 top
C8  61,64 180 top
C9  28,95 270 top
C10  28,101 270 top
C11  24,104 90 top
C12  24,94 90 top
C13  39,127 180 top
C14  73,114 90 top
C15  131.5,36 90 top
C16  74,107 0 top
C17  85,114 90 top
C18  122.5,16.5 0 top
C19  114.5,16.5 0 top
C20  124.5,10.5 0 top
C21  112.5,10.5 0 top
C22  86,101 0 top
C23  86,107 0 top
C24  90,165 90 top
C25  86,165 90 top
C26  116,132 0 top
CASE  not placed on the board
D1  67.75,83.25 270 top
D2  50,64 180 top
D3  50,67 180 top
D4  63,83 270 top
D5  109,101 270 top
D6  124.5,4.5 180 top
D7  112.5,4.5 180 top
D8  95,177 90 top
D9  122,168 90 top
D10  122,157 90 top
D11  122,147 90 top
F1  123,99 180 top
F2  108.75,184.5 0 top
FESH-COM  82.75,42.5 90 top
IC1  57.75,32.74 0 top
IC2  Lite-On LTV847S  [DIL16@1]  26,50 270 top
IC3  63,68 270 top
IC4  38,98 0 top
IC5  74,121 0 top
IC6  86,121 0 top
IC7  Lite-On LTV847S  [DIL16@2]  34,146 270 top
IC8  88,171 0 top
J1  0,80 90 top
J2  0,60 90 top
J3  0,40 90 top
J4  0,20 90 top
J5  157.25,23 270 top
J6  0,100 90 top
J7  0,160 90 top
J8  0,140 90 top
J9  0,120 90 top
L1  55,25.75 180 top
MON+  57.75,50.25 180 top
MON-  92.25,50.25 0 top
PWR1  37,117 270 top
PWR2  118,31.5 270 top
Q1  98,141 0 top
Q2  103,172 270 top
Q3  103,158 270 top
Q4  103,144 270 top
Q5  108,120 270 top
R1  17,80 0 top
R2  17,60 0 top
R3  17,40 0 top
R4  17,20 0 top
R5  68,34 270 top
R6  68,24 270 top
R7  12.75,6.5 180 top
R8  73,17 180 top
R9  58,92 90 top
R10  77,36 180 top
R11  77,29 180 top
R12  77,22 180 top
R13  44,64 0 top
R14  44,67 0 top
R15  56,64 0 top
R16  56,67 0 top
R17  58.25,84.75 270 top
R18  63,59 0 top
R19  75,53 0 top
R20  65,64 180 top
R21  120.75,80.25 0 top
R22  71,114 90 top
R23  85,64 315 top
R24  90,64 225 top
R25  90,59 315 top
R26  83,114 90 top
R27  85,59 45 top
R28  17,160 0 top
R29  17,140 0 top
R30  16.25,121.25 90 top
R31  92,165 270 top
R32  130.75,110.5 270 top
R33  98,172 90 top
R34  97,158 90 top
R35  96,146 90 top
R36  98,138 0 top
R37  103,120 270 top
R38  100,172 270 top
R39  99,158 270 top
R40  99,146 270 top
R41  123,130 90 top
R42  not placed on the board
RLY1  67.75,92.25 0 top
SW1  87,36 90 top
SW2  87,29 90 top
SW3  87,22 90 top
SW4  91.5,147 270 top
TB1  130,90 90 top
TB2  130,180 90 top
TB3  130,160 90 top
TB4  130,140 90 top
U$5  [TITLEBLOCK_PCB]  not placed on the board
U$6  [CASE:HAMMOND_1598D]  0,0 0 top
V-FESH  82.75,46.5 0 top

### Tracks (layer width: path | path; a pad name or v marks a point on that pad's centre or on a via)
12V_RLY  (via drill 0.51)
  Top 0.51: IC8.3 90.29,166.24 C24.2 R31.1 | TB4.1 127,140 124,137 124,132 123,132 | 123,132 C26.POS | IC7.12 37.27,144.73 35,147 35,150 | 35,150 35,153 37,155 37.7,155 IC7.16 | IC7.14 35.19,149.81 35,150 | 123,132 R41.2
  Top 0.54: R31.1 93.45,165.95 v93.5,166
  Bottom 0.54: 93.75,154.89 112.11,154.89 127,140 TB4.1 | 93.75,154.89 IC7.16 | v93.5,166 93.5,155.14 93.75,154.89
18V+
  Top 0.18: F1.1A 133.16,93.16 TB1.1
+2.500V  (via drill 0.51)
  Top 0.51: R5.THIS 71.41,32.5 84,32.5 85.75,34.25 SW1.1 89,33.73 v89,33.5 | 88.5,27.27 SW2.1 89,27.77 v89,28 | SW3.1 88.47,20.48 v89,21 | IC1.6 59.02,38.98 v59,39
  Bottom 0.51: R7.CW 14.23,5.23 17,8 40.09,8 R5.THIS 68,37.75 66.75,39 v59,39 | v89,21 v89,28 v89,33.5
+12V  (via drill 0.51)  (1 unrouted)
  Top 0.51: 27,49 27,45 29.46,44 IC2.10 | 27,49 27,52 28.81,53.81 IC2.14 36.81,53.81 v42,59 | IC2.12 27.27,48.73 27,49 | C7.1 66.25,69.7 v66.25,69.5 65.39,68.64 IC3.5 | IC5.2 73.95,117.05 77,114 77,107.2 C16.POS 77.2,104.8 83,99 v83,71
  Bottom 0.51: v42,59 55.75,59 v66.25,69.5 67.75,71 v83,71
+15V  (via drill 0.51)
  Top 0.51: IC6.2 85.95,117.05 89,114 89,107.2 C23.POS 89.25,106.95 89.25,104.75 86.95,102.45 C22.2 87.95,100 v88,100 | v73,100 72.95,99.95 C4.1 51,100.5 48.5,103 46.97,103 IC4.15 47,103.19 47,105 44,105 42,103 42,88 v50,80 | L1.2 52.25,25.75 46,32 46,44 51,49 v51,61
  Bottom 0.51: v73,100 v88,100 | v51,61 51,79 v50,80
+15V_STAB
  Top 0.51: D6.C 126.5,4.5 127.75,5.75 127.75,10.45 C20.POS | C18.2 125.75,16.5 127.75,14.5 127.75,10.55 C20.POS | C18.2 123.58,16.63 | PWR2.+VOUT 123.08,16.87 C18.2 | J5.9 158.67,16.67 157.5,15.5 155,15.5 150,10.5 C20.POS
+15VA
  Top 0.18: PWR1.+VOUT 42,108.08 42,110 40,112 28,112 24,108 C11.POS 24.8,106.2 26,105 26,99 27,98 29,98 30.25,96.75 30.25,94 | 30.25,94 30.25,93.32 IC4.1 | C9.2 30.2,94.05 30.25,94
+18V  (via drill 0.51)
  Top 0.51: C13.1 41.1,127 PWR1.+VIN 45.1,129 78,129 80,127 | IC5.3 78.46,118.46 80,120 80,127 | 80,127 82,129 90,129 92,127 92,120 91,119 88.83,119 IC6.3 107.75,99 D5.K F1.2A | C15.POS 124.4,39.2 PWR2.+VIN 123,40.6 v123,43 | F1.2A 112.84,65.16 v123,55 | F1.2A 113,99.16
  Bottom 0.51: v123,43 v123,55
-15V
  Top 0.18: C5.1 47.05,99.95 45.75,101.25 45.75,102.95 IC4.16
-15V_STAB  (via drill 0.51)
  Top 0.51: D7.A 110.82,4.93 109.25,6.5 109.25,10.45 C21.NEG 109.25,10.55 109.25,13.5 112.25,16.5 C19.1 113,17.05 113,22.42 PWR2.-VOUT 112.75,22.67 112.75,23.5 114.5,25.25 118.75,25.25 120.54,23.46 PWR2.TRM 120.5,22.46 v120.5,20 | J5.5 154.52,17.52 149.5,12.5 133.5,12.5 v126.25,19.75
  Bottom 0.51: v126.25,19.75 120.75,19.75 v120.5,20
-15VA
  Top 0.18: C12.NEG 24.8,91 31.65,91 IC4.2 31.65,99.9 31.5,100.05 | PWR1.-VOUT 32,107.08 32,109.75 32.75,110.5 37.75,110.5 39.54,108.71 PWR1.TRM 39.5,106.96 39.5,105 34.55,100.05 31.5,100.05 | 31.5,100.05 C10.2
AGND  (via drill 1.32)
  Top 0.5: 153,35 154.5,35 | 157,38 157,39 | 160,36 161,36 | 153,11 154.25,11 | 158,14 158,13 | 160,11 161,11 | 157,6 157,8 | 158,33 158,32
  other vias: 87.5,61.5
  pour Top (rank 2): 0,0 165,0 165,110 100.75,110 96,114.75 96,130 94,132 27,132 25,130 25,116.75 18.25,110 0,110
  pour Bottom (rank 2): 0,0 165,0 165,110 100.75,110 96,114.75 96,130 94,132 27,132 25,130 25,116.75 18.25,110 0,110
COM-A  (via drill 0.51)
  Top 0.18: J6.SHIELD1 12.54,97.46 11,99 11,101 J6.SHIELD2 23,102.54 23.74,101.8 C11.NEG C12.POS 24.25,95.95 C9.1 | PWR1.COM 34.5,106.96 34.5,105.75 31.5,105.75 30.38,104.63 IC4.28 29.25,101.95 C10.1 v28,103.5
  Bottom 0.18: J6.SHIELD2 27.04,102.54 v28,103.5
COM_REF  (via drill 0.51)
  Top 0.51: C4.2 C5.2 46.89,95.94 IC4.14 47.08,93 v47.75,93 | FESH-COM.TP 82.75,40.5 83.5,39.75 86.5,39.75 88.47,37.77 SW1.2 88.72,38 89,38 91,36 91,32 89.75,30.75 SW2.2 88.72,31 89,31 91,29 91,25 89.75,23.75 SW3.2 84.75,23.75 83,25.5 71.41,25.5 R6.OTHER 64.09,22.09 64,22 | R13.1 R14.1 43.05,68.05 45.75,70.75 62.8,70.75 C7.2 | C7.2 63.05,68.05 | 63.05,68.05 62.75,67.75 61.8,67.75 IC3.2 | 63.05,68.05 63.05,67.95 63.25,67.75 74.9,67.75 R27.1 | C7.2 63.05,81.28 D4.A 56.43,81.32 v49.5,88.25 | 64.04,31.41 IC1.4 61.63,29 62,29 64,27 64,22 | C2.1 59.05,20.25 61.1,20.25 C1.- 61.35,20 | 64,22 64,21 63,20 | R27.1 80,54 80,44.75 | R19.OTHER 86.43,56.22 R27.1 | MON-.TP 87.75,50.25 86.5,51.5 86.5,52.93 R19.OTHER | J5.1 150.52,28.48 126,53 R19.OTHER
  Top 2.5: 61.35,20 63,20
  Bottom 0.51: v49.5,88.25 49.5,91.25 v47.75,93
  pour Top: 63,81 52,81 52,78 45,78 45,71 63,71 63,72 68,72 68,56 73,56 73,39 83,39 83,42 80,45 80,54 84,58 75,67 75,78 63,78
  pour Top: 60,32 50,32 50,36 52,36 52,35 60,35 60,47 73,47 73,40 66,40 66,23 68,23 68,16 56,4 16.5,4 16.5,6.25 20.25,10 51,10 60,19
COM_RLY
  Top 0.51: R40.2 99.41,145.05 | R31.2 92.05,164 | IC8.2 88.87,173.87
  pour Top: 0,182 0,111 18,111 24,117 24,130.25 26.75,133 94.25,133 97,130.25 97,115 101,111 165,111 165,191 34.25,191 34.25,182
  pour Bottom: 0,182 0,111 18,111 24,117 24,130.25 26.75,133 94.25,133 97,130.25 97,115 101,111 165,111 165,191 34.25,191 34.25,182
COM_STAB  (via drill 0.51)
  Top 0.51: C19.2 115.5,16.55 | C21.POS C20.NEG | C19.2 115.45,10.75 C21.POS | C21.POS 115.7,6.02 D7.C | C20.NEG 121.3,6.02 D6.A | C19.2 PWR2.COM 115.96,23 v117,23 | J5.4 154.76,20.26 149,14.5 135.5,14.5 v134,16 | R25.2 92,57 v94,55 | C20.NEG 121.3,16 | 121.3,16 121.3,16.25 C18.1 | 121.3,16 v120,16
  Bottom 0.51: v94,55 116,33 116,24 v117,23 | v120,16 v134,16
  pour Top: 115.5,16 121,16 121,5.75 115.5,5.75
DRV  (via drill 0.51)
  Top 0.18: C6.2 61,62 60,63 60,63.95 C8.2 60.05,64.2 59.5,64.75 59.5,67.5 60.5,68.5 61.59,68.5 IC3.1 61.37,69 v61,69 | v116.8,80.25 R21.1
  Bottom 0.18: v61,69 72.25,80.25 v116.8,80.25
FAN-  (via drill 0.51)
  Top 0.51: Q5.2 118.16,123.84 113,129 113,131.8 C26.NEG 111,132 v111,134
  Bottom 0.51: TB4.2 112,135 v111,134
N$1
  Top 0.51: IC1.8 53.81,37.19 53,38 51.05,38 C3.2
N$2  (via drill 0.51)
  Top 0.51: MON+.TP 62.5,50.25 63.5,51.25 63.5,52.93 R19.THIS 62,53 v62,56 62.05,56.05 R18.1 | J5.6 158.67,29.33 157,31 152,31 v133,50 | v125,50 102,50 v98,46
  Bottom 0.51: v125,50 v133,50 | v62,56 64,56 69,51 84,51 89,46 v98,46
N$3
  Top 0.51: C17.1 R26.1 82.8,112.85 C23.NEG 83,106.8 83,104.25 85.05,102.2 C22.1 85.05,87.45 90.5,82 90.5,64.85 R24.1
N$4
  Top 0.18: J1.CONDUCTOR R1.1
N$5
  Top 0.18: RLY1.1 62.67,85.01 D4.C 62.93,84.75 61.75,84.75 60.8,83.8 R17.2
N$6
  Top 0.18: J2.CONDUCTOR R2.1
N$7
  Top 0.18: R17.1 58.25,90.8 R9.1 56.05,91.05 54.75,89.75 47.5,89.75 45.75,91.5 45.75,93.06 IC4.13
N$8
  Top 0.18: IC3.4 65.27,66.73 66,66 66,64.05 R20.1 65.95,62.95 65,62 C6.1 63.95,60.5 | R15.2 56.95,63.3 59.75,60.5 63.95,60.5 | 63.95,60.5 R18.2
N$9
  Top 0.51: F2.2A 125.5,184.5 TB2.1
N$10
  Top 0.18: J3.CONDUCTOR R3.1
N$11  (via drill 0.51)
  Top 0.18: R9.2 61.11,96.06 RLY1.10 63,95.73 63,94 65,92 75,92 77,90 v77,69 | R8.1 74.8,21.7 R12.2 | 68,29 R6.THIS | 68,29 R5.OTHER | R11.2 68,29 | v71,49 v71,53
  Bottom 0.18: R12.2 R11.2 R10.2 75.09,46.41 75,46.5 | 75,46.5 73.5,46.5 v71,49 | 75,46.5 V-FESH.TP | v77,69 77,59 v71,53
N$12
  Top 0.18: J4.CONDUCTOR R4.1
N$13
  Top 0.18: R1.2 17.95,66.05 22,62 22,59.08 IC2.1
N$14
  Top 0.51: TB2.4 123,165 D9.A 119.16,166 Q2.2
N$15  (via drill 0.51)
  Top 0.18: D3.A R14.2 46.25,67 v46.5,66.75
  Bottom 0.18: v46.5,66.75 46.5,66.25 31.5,51.25 29.83,51.25 IC2.13
N$16  (via drill 0.51)
  Top 0.18: RLY1.3 D1.C 66.07,84.93 v66,85
  Bottom 0.18: v66,85 52,85 27,60 27,42.5 28.25,41.25 29.67,41.25 IC2.9
N$17  (via drill 0.51)
  Top 0.18: 57.22,66.73 R16.2 v58,67 | IC3.3 61.23,66.73 v61,66.5 | v72.83,84.83 RLY1.5
  Bottom 0.18: v61,66.5 58.5,66.5 v58,67 58,70 v72.83,84.83
N$18
  Top 0.18: IC2.3 21.19,53.81 19,56 19,58.95 R2.2
N$19
  Top 0.51: C1.+ 60.2,24.9 C2.2 58.25,23.35 L1.1 56.48,26.38 IC1.2
N$20
  Top 0.18: D3.C R16.1
N$21
  Top 0.18: R3.2 17.95,45.7 21,48.75 22.17,48.75 IC2.5
N$22
  Top 0.18: R4.2 17.95,34.95 20,37 20,42.5 21,43.5 22.04,43.5 IC2.7
N$23  (via drill 0.51)
  Top 0.18: v33,103.25 31.82,103.25 IC4.27
  Bottom 0.18: J6.CONDUCTOR 29.75,100 v33,103.25
N$24
  Top 0.18: C8.1 R20.2
N$25
  Top 0.18: R10.1 SW1.COM
N$26  (via drill 0.51)
  Top 0.18: R7.WIPER 14.77,7.77 20,13 v50,13 | v71,15 71,16.8 R8.2
  Bottom 0.18: v50,13 69,13 v71,15
N$27
  Top 0.18: C17.2 R26.2 83,117.75 IC6.1
N$28
  Top 0.18: J1.SHIELD2 12.54,82.54 11,81 11,79 12.54,77.46 J1.SHIELD1
  Bottom 0.18: J1.SHIELD1 16.54,77.46 17,77 17,60.5 21,56.5 22.04,56.5 IC2.2
N$29
  Top 0.18: J2.SHIELD2 12.54,62.54 11,61 11,59 12.54,57.46 J2.SHIELD1 13.16,57 15,57 20.73,51.27 IC2.4
N$30
  Top 0.18: J7.CONDUCTOR R28.1
N$31
  Top 0.18: J3.SHIELD1 12.54,37.46 11,39 11,41 12.54,42.54 J3.SHIELD2
  Bottom 0.18: J3.SHIELD2 16.54,42.54 20,46 22,46 IC2.6
N$32
  Top 0.18: R11.1 SW2.COM
N$33
  Top 0.18: R12.1 SW3.COM
N$34
  Top 0.18: R36.1 Q1.1 96.95,140.05 93,144 93,146.97 SW4.COM
N$35
  Top 0.18: J8.CONDUCTOR R29.1
N$36
  Top 0.18: R30.1 13,120.3 J9.CONDUCTOR
N$37
  Top 0.51: R41.1 129.05,129.05 TB4.3
N$38
  Top 0.18: Q2.1 101.59,174.54 R38.1 R33.2
N$39
  Top 0.18: R28.2 25.08,160 IC7.1
N$40
  Top 0.18: R29.2 19,140 29,150 30,150 IC7.3
N$41
  Top 0.18: IC5.1 71.71,117.21 71.25,116.75 71.25,115.2 R22.2 C14.2
N$42
  Top 0.18: TB1.3 121.95,80 R21.2
N$43
  Top 0.18: J4.SHIELD1 12.54,17.46 11,19 11,21 12.54,22.54 J4.SHIELD2
  Bottom 0.18: J4.SHIELD2 14.54,22.54 22,30 22,40.92 IC2.8
N$44
  Top 0.18: R30.2 16.25,132.25 28.75,144.75 30.17,144.75 IC7.5
N$45
  Top 0.18: D2.C R15.1
N$46  (via drill 0.51)
  Top 0.18: 89.5,153 40.25,153 39.5,152.25 37.91,152.25 IC7.15 | v89.5,146 89.5,145.78 SW4.2 | 89.5,153 89.5,156.5 98,165 R33.1 | 89.5,153 v89.5,152.75
  Bottom 0.18: v89.5,152.75 v89.5,146
N$47
  Top 0.18: J7.SHIELD2 12.54,162.54 11,161 11,159.16 J7.SHIELD1 23.54,157.46 28.5,152.5 30.04,152.5 IC7.2
N$48
  Top 0.18: J8.SHIELD1 12.54,137.46 11,139 11,141 11.16,141 J8.SHIELD2
  Bottom 0.18: J8.SHIELD2 23.54,142.54 28,147 29.92,147 IC7.4
N$49
  Top 0.18: J9.SHIELD1 12.54,117.46 11,119 11,121 11.16,121 J9.SHIELD2
  Bottom 0.18: J9.SHIELD2 12.7,125.7 29,142 30,142 IC7.6
N$50
  Top 0.18: 90.03,151.03 SW4.1 | 90.03,151.03 96,157 96.95,157 R34.1 | IC7.13 47.02,147.27 50.75,151 90,151 90.03,151.03
N$51
  Top 0.51: TB3.2 D10.A 116.16,155 Q3.2
N$52  (via drill 0.51)
  Top 0.18: v96,144 R35.1
  Bottom 0.18: v96,144 95,143 40,143 39.25,142.25 37.87,142.25 IC7.11
N$53
  Top 0.18: R34.2 R39.1 99,159 100.5,160.5 102.96,160.5 Q3.1
N$54  (1 unrouted)
  Top 0.51: C14.1 R22.1 71,107.2 C16.NEG 70.8,106.95 80.5,97.25 80.5,68.5 R23.1
N$55
  Top 0.51: TB3.4 D11.A 114.16,145 Q4.2
N$56
  Top 0.18: 0.09,1.09 0.09,0.09 1.09,0.09
N$57
  Top 0.18: 97.5,146.95 R35.2 | 97.5,146.95 R40.1 102.59,146.95 Q4.1 | Q1.3 98,143.5 97.5,144 97.5,146.95
N$58
  Bottom 0.18: 0.09,1.09 0.09,0.09 1.09,0.09
N$59
  Bottom 0.18: 164.91,1.09 164.91,0.09 163.91,0.09
N$60
  Top 0.18: 164.91,1.09 164.91,0.09 163.91,0.09
N$61
  Top 0.18: 163.91,190.91 164.91,190.91 164.91,189.91
N$62
  Bottom 0.18: 164.91,189.91 164.91,190.91 163.91,190.91
N$63
  Bottom 0.18: 1.09,190.91 0.09,190.91 0.09,189.91
N$64
  Top 0.18: 1.09,190.91 0.09,190.91 0.09,189.91
OFF
  Top 0.18: D2.A R13.2 44.75,63.8 44.75,58.5 32.44,46.19 IC2.11
RLY+
  Top 0.51: D11.K 123,150 TB3.3 133,153 133,157 TB3.1 | TB3.1 123,160 D10.K | C25.2 85.71,166.24 IC8.1 85.17,169 84,169 83,170 83,177 85,179 D8.K 95,180.91 F2.1A 98.59,183.41 102,180 120,180 122,178 D9.K TB2.3 131,170 133,168 133,163 TB3.1
THRM
  Top 0.18: R37.CW Q5.1
  Bottom 0.18: TB4.4 106.73,125 R37.CW

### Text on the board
Top: Fesh-MOT Coils Rev:A | Fuse 1A | University of Toronto | Æ. Steinberg Labs | Relays + | Relays - | 1+ | Rly 1- | Rly 2+ | Rly 2- | not 2 | Rly 3+ | not 1 | Rly 3- | Fan+ | Fan- | Therm | Ther | Fuse 0.5A | +18V | 18V Com | Gate | Srce | V-Fesh | Com | - | 4% | + | - | 2% | + | - | 1% | +
Document: Case | AC-DC
tDocu: 198 (ref) | 0.5" | 163.5 | 8 pl | 143.5 | 123.5 | 103.5 | 83.5 | 63.5 | Hammond 1598D Faceplate (back view) | 43.5 | 23.5 | 0 | 58 (ref) | 13.41 | 0 | Fesh-MOT Coils | Æ Steinberg Labs | A. Stummer Aug'11 | A2 | 0.18mm(0.008") | 0.18mm(0.008") | 0.?mm(0.?") | 0.25mm(0.01") | 1) Connect shield of DB-9 to common.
